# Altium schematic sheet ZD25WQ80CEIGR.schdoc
size 127 x 101 mm
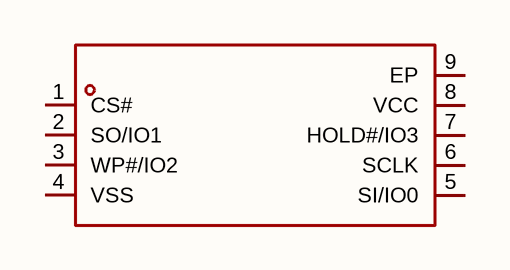
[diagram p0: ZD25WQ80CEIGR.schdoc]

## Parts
U?  zd25wq80ceigr  [USON-8_L3.0-W2.0-P0.50-BL-EP_ZD25XX]  (value not drawn)

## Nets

Not connected (* = marked no-connect by the designer): U? 1(CS#) 2(SO/IO1) 3(WP#/IO2) 4(VSS) 5(SI/IO0) 6(SCLK) 7(HOLD#/IO3) 8(VCC) 9(EP)

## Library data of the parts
U? = zd25wq80ceigr: 接口类型:SPI;存储容量:8Mbit;时钟频率(fc):104MHz;; Manufacturer: Zetta(澜智); AddInBom: yes; ModelId: 12a239e5c7384371915ecb51201bf581; ModelName: USON-8_L3.0-W2.0-H0.6-P0.50; ModelTransform: 118.8974,78.74,0,90,0,0,0,0,0; Interface: SPI; Memory Size: 8Mbit; Clock Frequency: 104MHz; Voltage - Supply: 1.65V~3.6V; Standby Supply Current: 0.1uA; Program / Erase Cycles: 100000次; Page Programming Time (Tpp): 1.5ms; Block Erase Time(tBE): 6ms; Data Retention - TDR (Year): 20年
